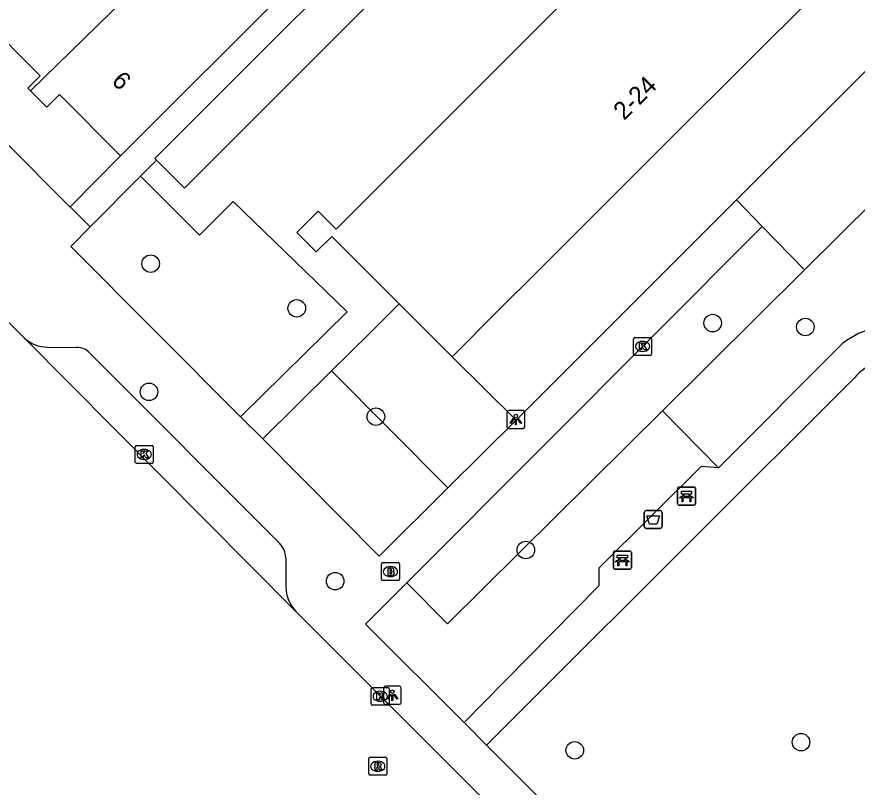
# Model space of a CAD drawing. Extents: x 159961 to 160856, y 382704 to 383353.
# Drawn here: x 160147.16 to 160194.04, y 383012.24 to 383055.21 of the extents above; entities that cross this region are included whole.
import ezdxf

# ---------------------------------------------------------------- set-up
doc = ezdxf.new("R2010")
doc.units = 0
for name, color, linetype in [('IMGEO_Afvalbak', 7, 'Continuous'), ('IMGEO_Bank', 7, 'Continuous'), ('IMGEO_Boom', 7, 'Continuous'), ('IMGEO_Brandkraan', 7, 'Continuous'), ('IMGEO_Groenvoorziening', 7, 'Continuous'), ('IMGEO_Kolk', 7, 'Continuous'), ('IMGEO_Lichtpunt', 7, 'Continuous'), ('IMGEO_Pand', 7, 'Continuous'), ('IMGEO_Pand_nummerreeks', 7, 'Continuous'), ('IMGEO_Rijbaan_lokaal_open', 7, 'Continuous'), ('IMGEO_Rioolput', 7, 'Continuous'), ('IMGEO_Voetpad_halfverhard', 7, 'Continuous'), ('IMGEO_Voetpad_open', 7, 'Continuous')]:
    doc.layers.add(name, color=color, linetype=linetype)

msp = doc.modelspace()

# ---------------------------------------------------------------- linework, layer by layer
at = {"layer": 'IMGEO_Afvalbak'}
for p, q in [((160182.169, 383026.765), (160182.169, 383027.565)), ((160182.169, 383027.565), (160182.169, 383026.765)), ((160182.269, 383027.665), (160183.059, 383027.665)), ((160183.059, 383027.665), (160182.269, 383027.665)), ((160183.159, 383027.565), (160183.159, 383026.765)), ((160183.159, 383026.765), (160183.159, 383027.565)), ((160183.059, 383026.665), (160182.269, 383026.665)), ((160182.269, 383026.665), (160183.059, 383026.665))]:
    msp.add_line(p, q, dxfattribs=at)
msp.add_lwpolyline([(160182.312, 383027.379), (160183.016, 383027.379), (160182.867, 383026.909), (160182.461, 383026.909), (160182.312, 383027.379)], dxfattribs=at)
for centre, start, end in [((160182.269, 383027.565), 90, 180), ((160182.269, 383027.565), 90, 180), ((160183.059, 383027.565), 0, 90), ((160183.059, 383027.565), 360, 90), ((160182.269, 383026.765), 180, 270), ((160182.269, 383026.765), 180, 270), ((160183.059, 383026.765), 270, 0), ((160183.059, 383026.765), 270, 0)]:
    msp.add_arc(centre, 0.1, start, end, dxfattribs=at)
at = {"layer": 'IMGEO_Bank'}
for p, q in [((160184.023, 383028.045), (160184.023, 383028.886)), ((160184.023, 383028.886), (160184.023, 383028.045)), ((160184.098, 383028.97), (160184.939, 383028.97)), ((160184.939, 383028.97), (160184.098, 383028.97)), ((160185.023, 383028.895), (160185.023, 383028.054)), ((160185.023, 383028.054), (160185.023, 383028.895)), ((160184.72, 383028.368), (160184.327, 383028.368)), ((160184.332, 383028.476), (160184.332, 383028.582)), ((160184.376, 383028.582), (160184.376, 383028.476)), ((160184.664, 383028.588), (160184.382, 383028.588)), ((160184.382, 383028.47), (160184.664, 383028.47)), ((160184.67, 383028.476), (160184.67, 383028.582)), ((160184.714, 383028.582), (160184.714, 383028.476)), ((160184.948, 383027.97), (160184.107, 383027.97)), ((160184.107, 383027.97), (160184.948, 383027.97)), ((160180.521, 383025.405), (160181.362, 383025.405)), ((160181.362, 383025.405), (160180.521, 383025.405)), ((160180.446, 383024.48), (160180.446, 383025.321)), ((160180.446, 383025.321), (160180.446, 383024.48)), ((160180.755, 383024.911), (160180.755, 383025.017)), ((160180.799, 383025.017), (160180.799, 383024.911)), ((160181.087, 383025.023), (160180.805, 383025.023)), ((160181.093, 383024.911), (160181.093, 383025.017)), ((160181.137, 383025.017), (160181.137, 383024.911)), ((160181.446, 383025.33), (160181.446, 383024.489)), ((160181.446, 383024.489), (160181.446, 383025.33)), ((160181.143, 383024.803), (160180.75, 383024.803)), ((160180.805, 383024.905), (160181.087, 383024.905)), ((160181.371, 383024.405), (160180.53, 383024.405)), ((160180.53, 383024.405), (160181.371, 383024.405))]:
    msp.add_line(p, q, dxfattribs=at)
for points in [[(160184.326, 383028.588), (160184.24, 383028.588), (160184.24, 383028.749), (160184.803, 383028.749), (160184.803, 383028.588), (160184.72, 383028.588)], [(160184.27, 383028.368), (160184.128, 383028.368), (160184.24, 383028.47), (160184.326, 383028.47)], [(160184.32, 383028.361), (160184.32, 383028.154), (160184.277, 383028.154), (160184.277, 383028.361)], [(160184.72, 383028.47), (160184.803, 383028.47), (160184.915, 383028.368), (160184.776, 383028.368)], [(160184.77, 383028.361), (160184.77, 383028.154), (160184.726, 383028.154), (160184.726, 383028.361)], [(160180.749, 383025.023), (160180.663, 383025.023), (160180.663, 383025.184), (160181.226, 383025.184), (160181.226, 383025.023), (160181.143, 383025.023)], [(160180.693, 383024.803), (160180.551, 383024.803), (160180.663, 383024.905), (160180.749, 383024.905)], [(160180.743, 383024.796), (160180.743, 383024.589), (160180.7, 383024.589), (160180.7, 383024.796)], [(160181.143, 383024.905), (160181.226, 383024.905), (160181.338, 383024.803), (160181.199, 383024.803)], [(160181.193, 383024.796), (160181.193, 383024.589), (160181.149, 383024.589), (160181.149, 383024.796)]]:
    msp.add_lwpolyline(points, dxfattribs=at)
for centre, radius, start, end in [((160184.101, 383028.892), 0.0779, 92.4484, 184.2845), ((160184.101, 383028.892), 0.0779, 92.4484, 184.2845), ((160184.945, 383028.892), 0.0779, 2.4484, 94.2845), ((160184.945, 383028.892), 0.0779, 2.4484, 94.2845), ((160184.27, 383028.361), 0.00671, 2.8957, 87.1043), ((160184.327, 383028.361), 0.00671, 92.8957, 177.1043), ((160184.325, 383028.581), 0.00671, 2.8957, 87.1043), ((160184.325, 383028.477), 0.00671, 272.8957, 357.1043), ((160184.382, 383028.581), 0.00671, 92.8957, 177.1043), ((160184.382, 383028.477), 0.00671, 182.8957, 267.1043), ((160184.664, 383028.581), 0.00671, 2.8957, 87.1043), ((160184.664, 383028.477), 0.00671, 272.8957, 357.1043), ((160184.721, 383028.581), 0.00671, 92.8957, 177.1043), ((160184.721, 383028.477), 0.00671, 182.8957, 267.1043), ((160184.719, 383028.361), 0.00671, 2.8957, 87.1043), ((160184.776, 383028.361), 0.00671, 92.8957, 177.1043), ((160184.101, 383028.048), 0.0779, 182.4484, 274.2845), ((160184.101, 383028.048), 0.0779, 182.4484, 274.2845), ((160184.945, 383028.048), 0.0779, 272.4484, 4.2845), ((160184.945, 383028.048), 0.0779, 272.4484, 4.2845), ((160180.524, 383025.327), 0.0779, 92.4484, 184.2845), ((160180.524, 383025.327), 0.0779, 92.4484, 184.2845), ((160181.368, 383025.327), 0.0779, 2.4484, 94.2845), ((160181.368, 383025.327), 0.0779, 2.4484, 94.2845), ((160180.748, 383025.016), 0.00671, 2.8957, 87.1043), ((160180.805, 383025.016), 0.00671, 92.8957, 177.1043), ((160181.087, 383025.016), 0.00671, 2.8957, 87.1043), ((160181.144, 383025.016), 0.00671, 92.8957, 177.1043), ((160180.524, 383024.483), 0.0779, 182.4484, 274.2845), ((160180.524, 383024.483), 0.0779, 182.4484, 274.2845), ((160180.693, 383024.796), 0.00671, 2.8957, 87.1043), ((160180.75, 383024.796), 0.00671, 92.8957, 177.1043), ((160180.748, 383024.912), 0.00671, 272.8957, 357.1043), ((160180.805, 383024.912), 0.00671, 182.8957, 267.1043), ((160181.087, 383024.912), 0.00671, 272.8957, 357.1043), ((160181.144, 383024.912), 0.00671, 182.8957, 267.1043), ((160181.142, 383024.796), 0.00671, 2.8957, 87.1043), ((160181.199, 383024.796), 0.00671, 92.8957, 177.1043), ((160181.368, 383024.483), 0.0779, 272.4484, 4.2845), ((160181.368, 383024.483), 0.0779, 272.4484, 4.2845)]:
    msp.add_arc(centre, radius, start, end, dxfattribs=at)
at = {"layer": 'IMGEO_Boom'}
for centre in [(160154.626, 383041.435), (160162.778, 383038.944), (160185.978, 383038.124), (160191.155, 383037.907), (160154.535, 383034.286), (160167.194, 383032.906), (160175.557, 383025.463), (160164.92, 383023.727), (160190.907, 383014.744), (160178.288, 383014.291)]:
    msp.add_circle(centre, 0.489, dxfattribs=at)
at = {"layer": 'IMGEO_Brandkraan'}
for p, q in [((160167.506, 383023.836), (160167.506, 383024.688)), ((160167.581, 383024.762), (160168.433, 383024.762)), ((160167.994, 383024.542), (160168.019, 383024.542)), ((160168.507, 383024.688), (160168.507, 383023.836)), ((160168.433, 383023.762), (160167.581, 383023.762)), ((160168.017, 383023.982), (160167.992, 383023.982))]:
    msp.add_line(p, q, dxfattribs=at)
for points in [[(160167.506, 383023.836), (160167.506, 383024.688)], [(160167.581, 383024.762), (160168.433, 383024.762)], [(160168.507, 383024.688), (160168.507, 383023.836)], [(160167.854, 383024.462), (160167.854, 383024.062), (160168.067, 383024.062)], [(160168.085, 383024.462), (160167.854, 383024.462)], [(160168.033, 383024.381), (160167.979, 383024.381), (160167.979, 383024.305)], [(160167.979, 383024.305), (160168.032, 383024.305)], [(160168.041, 383024.229), (160167.979, 383024.229), (160167.979, 383024.148)], [(160167.979, 383024.148), (160168.041, 383024.148)], [(160168.433, 383023.762), (160167.581, 383023.762)]]:
    msp.add_lwpolyline(points, dxfattribs=at)
for centre, radius, start, end in [((160167.583, 383024.686), 0.0765, 91.552, 178.448), ((160167.583, 383024.686), 0.0765, 91.552, 178.448), ((160168.431, 383024.686), 0.0765, 1.552, 88.448), ((160168.431, 383024.686), 0.0765, 1.552, 88.448), ((160168.034, 383024.343), 0.0379, 267.8285, 90.9355), ((160168.042, 383024.188), 0.0404, 269.8759, 90.5077), ((160168.073, 383024.313), 0.251, 268.6676, 293.5347), ((160168.089, 383024.317), 0.145, 59.4692, 91.5367), ((160168.114, 383024.364), 0.0922, 285.5137, 58.1501), ((160168.119, 383024.172), 0.105, 301.3115, 78.989), ((160167.583, 383023.838), 0.0765, 181.552, 268.448), ((160167.583, 383023.838), 0.0765, 181.552, 268.448), ((160168.431, 383023.838), 0.0765, 271.552, 358.448), ((160168.431, 383023.838), 0.0765, 271.552, 358.448)]:
    msp.add_arc(centre, radius, start, end, dxfattribs=at)
for centre, major_axis, ratio, start_param, end_param in [((160167.993, 383024.262), (-0.387, 0.002), 0.722429, 4.712389, 7.853982), ((160168.018, 383024.262), (-0.39, 0.002), 0.717154, 1.570796, 4.712389)]:
    msp.add_ellipse(centre, major_axis=major_axis, ratio=ratio, start_param=start_param, end_param=end_param, dxfattribs=at)
at = {"layer": 'IMGEO_Groenvoorziening'}
for points in [[(160154.068, 383046.323), (160157.349, 383043.027), (160159.228, 383044.897), (160165.6, 383038.75), (160159.644, 383032.889)], [(160191.105, 383041.088), (160183.175, 383033.223)], [(160164.715, 383035.46), (160166.831, 383037.549), (160168.489, 383039.198)], [(160171.443, 383036.241), (160175.019, 383032.716)], [(160160.879, 383031.671), (160164.715, 383035.46)], [(160164.715, 383035.46), (160171.216, 383028.941)], [(160183.175, 383033.223), (160171.194, 383021.339), (160168.926, 383023.636)], [(160183.175, 383033.223), (160186.3, 383030.051)]]:
    msp.add_lwpolyline(points, dxfattribs=at)
at = {"layer": 'IMGEO_Kolk'}
for p, q in [((160181.572, 383036.399), (160181.572, 383037.251)), ((160181.647, 383037.325), (160182.499, 383037.325)), ((160182.573, 383037.251), (160182.573, 383036.399)), ((160182.06, 383037.105), (160182.085, 383037.105)), ((160182.499, 383036.325), (160181.647, 383036.325)), ((160182.083, 383036.545), (160182.058, 383036.545)), ((160153.769, 383030.373), (160153.769, 383031.225)), ((160153.844, 383031.299), (160154.696, 383031.299)), ((160154.257, 383031.079), (160154.282, 383031.079)), ((160154.77, 383031.225), (160154.77, 383030.373)), ((160154.696, 383030.299), (160153.844, 383030.299)), ((160154.28, 383030.519), (160154.255, 383030.519)), ((160166.933, 383016.879), (160166.933, 383017.731)), ((160167.008, 383017.805), (160167.86, 383017.805)), ((160167.421, 383017.585), (160167.446, 383017.585)), ((160167.934, 383017.731), (160167.934, 383016.879)), ((160167.444, 383017.025), (160167.419, 383017.025)), ((160167.86, 383016.805), (160167.008, 383016.805))]:
    msp.add_line(p, q, dxfattribs=at)
for points in [[(160181.572, 383036.399), (160181.572, 383037.251)], [(160181.647, 383037.325), (160182.499, 383037.325)], [(160182.573, 383037.251), (160182.573, 383036.399)], [(160181.893, 383037.025), (160182.016, 383037.025), (160182.016, 383036.874), (160182.146, 383037.025), (160182.31, 383037.025), (160182.164, 383036.874), (160182.317, 383036.625), (160182.165, 383036.625), (160182.08, 383036.789), (160182.016, 383036.722), (160182.016, 383036.625), (160181.893, 383036.625), (160181.893, 383037.025)], [(160182.499, 383036.325), (160181.647, 383036.325)], [(160153.769, 383030.373), (160153.769, 383031.225)], [(160153.844, 383031.299), (160154.696, 383031.299)], [(160154.77, 383031.225), (160154.77, 383030.373)], [(160154.09, 383030.999), (160154.213, 383030.999), (160154.213, 383030.848), (160154.343, 383030.999), (160154.507, 383030.999), (160154.361, 383030.848), (160154.514, 383030.599), (160154.362, 383030.599), (160154.277, 383030.763), (160154.213, 383030.696), (160154.213, 383030.599), (160154.09, 383030.599), (160154.09, 383030.999)], [(160154.696, 383030.299), (160153.844, 383030.299)], [(160166.933, 383016.879), (160166.933, 383017.731)], [(160167.008, 383017.805), (160167.86, 383017.805)], [(160167.254, 383017.505), (160167.377, 383017.505), (160167.377, 383017.354), (160167.507, 383017.505), (160167.671, 383017.505), (160167.525, 383017.354), (160167.678, 383017.105), (160167.526, 383017.105), (160167.441, 383017.269), (160167.377, 383017.202), (160167.377, 383017.105), (160167.254, 383017.105), (160167.254, 383017.505)], [(160167.934, 383017.731), (160167.934, 383016.879)], [(160167.86, 383016.805), (160167.008, 383016.805)]]:
    msp.add_lwpolyline(points, dxfattribs=at)
for centre, start, end in [((160181.649, 383037.249), 91.552, 178.448), ((160181.649, 383037.249), 91.552, 178.448), ((160182.497, 383037.249), 1.552, 88.448), ((160182.497, 383037.249), 1.552, 88.448), ((160181.649, 383036.401), 181.552, 268.448), ((160181.649, 383036.401), 181.552, 268.448), ((160182.497, 383036.401), 271.552, 358.448), ((160182.497, 383036.401), 271.552, 358.448), ((160153.846, 383031.223), 91.552, 178.448), ((160153.846, 383031.223), 91.552, 178.448), ((160154.694, 383031.223), 1.552, 88.448), ((160154.694, 383031.223), 1.552, 88.448), ((160153.846, 383030.375), 181.552, 268.448), ((160153.846, 383030.375), 181.552, 268.448), ((160154.694, 383030.375), 271.552, 358.448), ((160154.694, 383030.375), 271.552, 358.448), ((160167.01, 383017.729), 91.552, 178.448), ((160167.01, 383017.729), 91.552, 178.448), ((160167.858, 383017.729), 1.552, 88.448), ((160167.858, 383017.729), 1.552, 88.448), ((160167.01, 383016.881), 181.552, 268.448), ((160167.01, 383016.881), 181.552, 268.448), ((160167.858, 383016.881), 271.552, 358.448), ((160167.858, 383016.881), 271.552, 358.448)]:
    msp.add_arc(centre, 0.0765, start, end, dxfattribs=at)
for centre, major_axis, ratio, start_param, end_param in [((160182.059, 383036.825), (-0.387, 0.002), 0.722429, 4.712389, 7.853982), ((160182.084, 383036.825), (-0.39, 0.002), 0.717154, 1.570796, 4.712389), ((160154.256, 383030.799), (-0.387, 0.002), 0.722429, 4.712389, 7.853982), ((160154.281, 383030.799), (-0.39, 0.002), 0.717154, 1.570796, 4.712389), ((160167.42, 383017.305), (-0.387, 0.002), 0.722429, 4.712389, 7.853982), ((160167.445, 383017.305), (-0.39, 0.002), 0.717154, 1.570796, 4.712389)]:
    msp.add_ellipse(centre, major_axis=major_axis, ratio=ratio, start_param=start_param, end_param=end_param, dxfattribs=at)
at = {"layer": 'IMGEO_Lichtpunt'}
for p, q in [((160174.499, 383033.147), (160174.499, 383032.34)), ((160174.499, 383033.147), (160174.499, 383032.34)), ((160175.401, 383033.242), (160174.593, 383033.242)), ((160175.401, 383033.242), (160174.593, 383033.242)), ((160175.495, 383032.34), (160175.495, 383033.147)), ((160175.495, 383032.34), (160175.495, 383033.147)), ((160174.593, 383032.246), (160175.401, 383032.246)), ((160174.593, 383032.246), (160175.401, 383032.246)), ((160167.612, 383017.768), (160167.612, 383016.961)), ((160167.612, 383017.768), (160167.612, 383016.961)), ((160168.514, 383017.863), (160167.706, 383017.863)), ((160168.514, 383017.863), (160167.706, 383017.863)), ((160168.608, 383016.961), (160168.608, 383017.768)), ((160168.608, 383016.961), (160168.608, 383017.768)), ((160167.706, 383016.867), (160168.514, 383016.867)), ((160167.706, 383016.867), (160168.514, 383016.867))]:
    msp.add_line(p, q, dxfattribs=at)
for points in [[(160174.873, 383032.811), (160174.912, 383032.783), (160174.724, 383032.521), (160174.686, 383032.548), (160174.873, 383032.811)], [(160174.975, 383032.763), (160175.022, 383032.763), (160175.022, 383032.441), (160174.975, 383032.441), (160174.975, 383032.763)], [(160175.085, 383032.783), (160175.123, 383032.81), (160175.31, 383032.548), (160175.271, 383032.52), (160175.085, 383032.783)], [(160167.986, 383017.432), (160168.025, 383017.404), (160167.837, 383017.142), (160167.799, 383017.169), (160167.986, 383017.432)], [(160168.088, 383017.384), (160168.135, 383017.384), (160168.135, 383017.062), (160168.088, 383017.062), (160168.088, 383017.384)], [(160168.198, 383017.404), (160168.236, 383017.431), (160168.423, 383017.169), (160168.384, 383017.141), (160168.198, 383017.404)]]:
    msp.add_lwpolyline(points, dxfattribs=at)
for centre in [(160174.998, 383032.945), (160168.111, 383017.566)]:
    msp.add_circle(centre, 0.0994, dxfattribs=at)
for centre, start, end in [((160174.593, 383033.147), 90, 180), ((160174.593, 383033.147), 90, 180), ((160175.401, 383033.147), 0, 90), ((160175.401, 383033.147), 0, 90), ((160174.593, 383032.34), 180, 270), ((160174.593, 383032.34), 180, 270), ((160175.401, 383032.34), 270, 0), ((160175.401, 383032.34), 270, 360), ((160167.706, 383017.768), 90, 180), ((160167.706, 383017.768), 90, 180), ((160168.514, 383017.768), 0, 90), ((160168.514, 383017.768), 0, 90), ((160167.706, 383016.961), 180, 270), ((160167.706, 383016.961), 180, 270), ((160168.514, 383016.961), 270, 0), ((160168.514, 383016.961), 270, 360)]:
    msp.add_arc(centre, 0.0946, start, end, dxfattribs=at)
at = {"layer": 'IMGEO_Pand'}
for points in [[(160168.489, 383039.198), (160164.729, 383042.96), (160163.868, 383042.099), (160162.785, 383043.182), (160163.973, 383044.369), (160164.973, 383043.367), (160190.421, 383068.795), (160197.216, 383061.995), (160193.896, 383058.678), (160191.768, 383056.551), (160183.71, 383048.499), (160181.57, 383046.36), (160176.172, 383040.966), (160174.057, 383038.854), (160171.443, 383036.241)], [(160176.279, 383066.437), (160176.223, 383066.382), (160176.734, 383065.871), (160156.507, 383045.659), (160154.956, 383047.211)], [(160154.956, 383047.211), (160154.864, 383047.303), (160170.898, 383063.324)], [(160154.637, 383057.652), (160147.926, 383051.079)], [(160161.188, 383055.671), (160158.932, 383053.425), (160156.482, 383050.986), (160152.938, 383047.458)], [(160147.926, 383051.079), (160147.775, 383051.231), (160148.455, 383051.908), (160145.266, 383055.111), (160144.589, 383054.436), (160143.677, 383055.352)], [(160152.938, 383047.458), (160149.539, 383050.873), (160148.832, 383050.169), (160147.926, 383051.079)], [(160168.489, 383039.198), (160171.443, 383036.241)]]:
    msp.add_lwpolyline(points, dxfattribs=at)
at = {"layer": 'IMGEO_Rijbaan_lokaal_open'}
for points in [[(160187.319, 383044.997), (160201.41, 383059.066)], [(160188.747, 383043.516), (160187.319, 383044.997)], [(160195.025, 383044.976), (160191.105, 383041.088)], [(160188.747, 383043.516), (160191.105, 383041.088)], [(160147.587, 383037.283), (160144.059, 383040.805)], [(160162.731, 383022.038), (160147.587, 383037.283)], [(160183.044, 383001.73), (160162.803, 383021.966), (160162.731, 383022.038)]]:
    msp.add_lwpolyline(points, dxfattribs=at)
at = {"layer": 'IMGEO_Rioolput'}
for p, q in [((160166.798, 383012.975), (160166.798, 383013.827)), ((160166.873, 383013.901), (160167.725, 383013.901)), ((160167.799, 383013.827), (160167.799, 383012.975)), ((160167.286, 383013.681), (160167.311, 383013.681)), ((160167.725, 383012.901), (160166.873, 383012.901)), ((160167.309, 383013.121), (160167.284, 383013.121))]:
    msp.add_line(p, q, dxfattribs=at)
for points in [[(160166.798, 383012.975), (160166.798, 383013.827)], [(160166.873, 383013.901), (160167.725, 383013.901)], [(160167.799, 383013.827), (160167.799, 383012.975)], [(160167.387, 383013.599), (160167.135, 383013.601), (160167.135, 383013.201)], [(160167.135, 383013.201), (160167.259, 383013.201), (160167.259, 383013.363), (160167.27, 383013.363)], [(160167.313, 383013.52), (160167.259, 383013.52), (160167.259, 383013.439)], [(160167.259, 383013.439), (160167.311, 383013.439)], [(160167.317, 383013.334), (160167.388, 383013.201), (160167.528, 383013.201), (160167.463, 383013.327)], [(160167.725, 383012.901), (160166.873, 383012.901)]]:
    msp.add_lwpolyline(points, dxfattribs=at)
for centre, radius, start, end in [((160166.875, 383013.825), 0.0765, 91.552, 178.448), ((160166.875, 383013.825), 0.0765, 91.552, 178.448), ((160167.723, 383013.825), 0.0765, 1.552, 88.448), ((160167.723, 383013.825), 0.0765, 1.552, 88.448), ((160167.269, 383013.31), 0.0533, 26.0293, 88.6989), ((160167.295, 383013.628), 0.19, 274.7715, 282.9687), ((160167.319, 383013.424), 0.0964, 77.0061, 93.1865), ((160167.333, 383013.481), 0.0378, 276.6634, 79.6772), ((160167.386, 383013.489), 0.109, 350.3612, 89.416), ((160167.384, 383013.489), 0.112, 277.5842, 350.9817), ((160167.368, 383013.274), 0.108, 29.5134, 73.7905), ((160166.875, 383012.977), 0.0765, 181.552, 268.448), ((160166.875, 383012.977), 0.0765, 181.552, 268.448), ((160167.723, 383012.977), 0.0765, 271.552, 358.448), ((160167.723, 383012.977), 0.0765, 271.552, 358.448)]:
    msp.add_arc(centre, radius, start, end, dxfattribs=at)
for centre, major_axis, ratio, start_param, end_param in [((160167.285, 383013.401), (-0.387, 0.002), 0.722429, 4.712389, 7.853982), ((160167.31, 383013.401), (-0.39, 0.002), 0.717154, 1.570796, 4.712389)]:
    msp.add_ellipse(centre, major_axis=major_axis, ratio=ratio, start_param=start_param, end_param=end_param, dxfattribs=at)
at = {"layer": 'IMGEO_Voetpad_halfverhard'}
for points in [[(160193.234, 383036.994), (160186.3, 383030.051)], [(160193.89, 383035.068), (160175.638, 383016.839), (160173.37, 383014.574)], [(160186.3, 383030.051), (160185.338, 383030.129), (160179.638, 383024.448), (160179.628, 383023.471), (160174.366, 383018.127), (160172.109, 383015.835)]]:
    msp.add_lwpolyline(points, dxfattribs=at)
for centre, radius, start, end in [((160196.276, 383033.011), 5.012, 80.154, 127.3716), ((160196.274, 383033.017), 3.145, 80.9039, 139.2857)]:
    msp.add_arc(centre, radius, start, end, dxfattribs=at)
at = {"layer": 'IMGEO_Voetpad_open'}
for points in [[(160095.492, 383099.518), (160150.103, 383044.635), (160150.129, 383044.609)], [(160150.129, 383044.609), (160152.938, 383047.458)], [(160154.068, 383046.323), (160154.956, 383047.211)], [(160151.257, 383043.497), (160154.068, 383046.323)], [(160187.319, 383044.997), (160175.019, 383032.716)], [(160151.257, 383043.497), (160150.129, 383044.609)], [(160159.644, 383032.889), (160150.167, 383042.403), (160151.257, 383043.497)], [(160168.926, 383023.636), (160176.534, 383031.267), (160188.747, 383043.516)], [(160148.868, 383036.786), (160150.495, 383036.77)], [(160151.227, 383036.449), (160161.824, 383025.843)], [(160160.879, 383031.671), (160159.644, 383032.889)], [(160175.019, 383032.716), (160171.216, 383028.941)], [(160171.216, 383028.941), (160167.371, 383025.123), (160160.879, 383031.671)], [(160162.167, 383025.033), (160162.165, 383023.386)], [(160172.109, 383015.835), (160166.62, 383021.323), (160168.926, 383023.636)], [(160173.37, 383014.574), (160172.109, 383015.835)], [(160186.482, 383001.467), (160173.37, 383014.574)]]:
    msp.add_lwpolyline(points, dxfattribs=at)
for centre, radius, start, end in [((160148.882, 383038.722), 1.936, 228.0092, 269.5804), ((160150.523, 383035.838), 0.932, 40.9354, 91.7073), ((160160.883, 383024.967), 1.286, 2.9538, 42.9473), ((160164.218, 383023.455), 2.054, 181.9315, 223.6218)]:
    msp.add_arc(centre, radius, start, end, dxfattribs=at)

# ---------------------------------------------------------------- texts
at = {"layer": 'IMGEO_Pand_nummerreeks'}
for s, rotation, p in [('6', 314.9369, (160152.398, 383051.566)), ('2-24', 44.9789, (160181.045, 383049.398))]:
    msp.add_text(s, height=1, rotation=rotation, dxfattribs=at).set_placement(p)

doc.saveas('drawing.dxf')
